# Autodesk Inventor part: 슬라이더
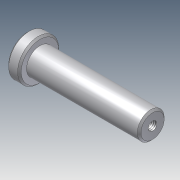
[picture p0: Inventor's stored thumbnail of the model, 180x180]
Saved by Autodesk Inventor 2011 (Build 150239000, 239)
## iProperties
Created: 2011-04
Part Number: 슬라이더
Document SubType Name: Modeling
Designer: 한국산업디자인학원 [http://gmhk.co.kr]
Density: 1 g/cm^3
Author: pww
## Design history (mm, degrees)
sketch "스케치1"
  geometry: L1 (-7, 0)-(63, 0); L2 (63, 0)-(63, 7.5); L3 (63, 7.5)-(0, 7.5); L4 (-7, 0)-(-7, 11.5); L5 (-7, 11.5)-(0, 11.5); L6 (0, 11.5)-(0, 7.5); 1 further point
  constraints: 12 end point, 3 perpendicular, 2 horizontal, 2 point on line, 1 parallel
  dimensions: "d1" = 70 distance of L1.start L1.end; "d19" = 15 diameter of L3 L1; "d20" = 7 distance of L4.end L5.end; "d21" = 23 diameter of L5 L1
revolve "회전1" stored, may be unused: angle "d4" = 90 deg
chamfer "모따기1" distance "d16" = 1; stored, may be unused: second distance "d17" = 2, angle "d18" = 45 deg
hole "구멍2" diameter "d24" = 4.917; stored, may be unused: countersink angle "d28" = 90 deg, drill point angle "d30" = 118 deg; dims "d22" = 10, "d23" = 10, "d25" = 10, "d26" = 4, "d27" = 2, "d29" = 13
node "솔리드1"
